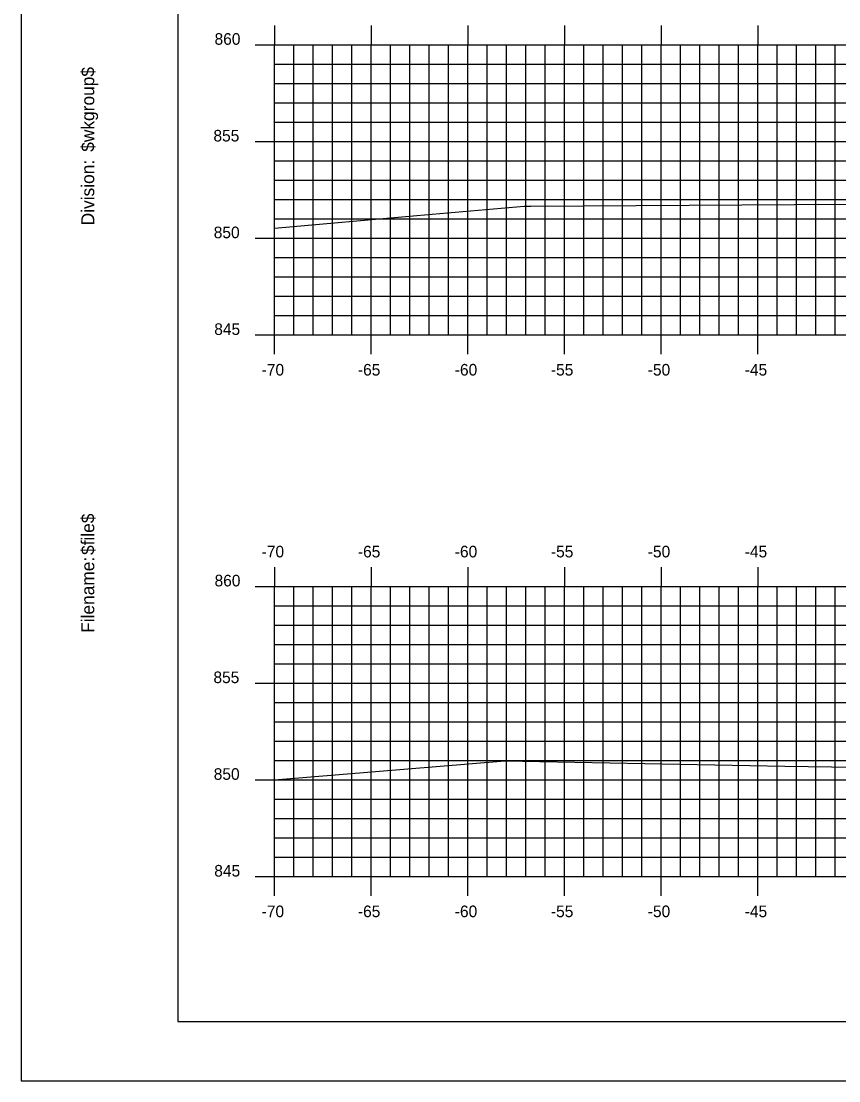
# Model space of a CAD drawing. Extents: x 2194738 to 2195190, y 863888 to 863998.
# Drawn here: x 2194837.2 to 2194879.4, y 863888.4 to 863943.2 of the extents above; entities that cross this region are included whole.
import ezdxf

# ---------------------------------------------------------------- set-up
doc = ezdxf.new("R2010")
doc.units = 0
for name, color, linetype in [('BORDER', 7, 'Continuous'), ('H_V ANNOTATION', 7, 'Continuous'), ('MAJOR', 7, 'Continuous'), ('MINOR', 7, 'Continuous'), ('PLOT BOUNDARY', 7, 'Continuous'), ('S_Roadway_Centerline', 7, 'Continuous')]:
    doc.layers.add(name, color=color, linetype=linetype)

msp = doc.modelspace()

# ---------------------------------------------------------------- linework, layer by layer
at = {"layer": 'BORDER'}
msp.add_lwpolyline([(2194845.256, 863891.446), (2195005.256, 863891.446), (2195005.256, 863996.446), (2194845.256, 863996.446)], close=True, dxfattribs=at)
at = {"layer": 'MAJOR'}
for p, q in [((2194850.256, 863942.948), (2194850.256, 863941.946)), ((2194855.256, 863942.948), (2194855.256, 863941.946)), ((2194860.256, 863942.948), (2194860.256, 863941.946)), ((2194865.256, 863942.948), (2194865.256, 863941.946)), ((2194870.256, 863942.948), (2194870.256, 863941.946)), ((2194875.256, 863942.948), (2194875.256, 863941.946)), ((2194849.254, 863941.946), (2194850.256, 863941.946)), ((2194850.256, 863941.946), (2194990.256, 863941.946)), ((2194850.256, 863926.946), (2194850.256, 863941.946)), ((2194850.256, 863926.946), (2194850.256, 863941.946)), ((2194855.256, 863926.946), (2194855.256, 863941.946)), ((2194860.256, 863926.946), (2194860.256, 863941.946)), ((2194865.256, 863926.946), (2194865.256, 863941.946)), ((2194870.256, 863926.946), (2194870.256, 863941.946)), ((2194875.256, 863926.946), (2194875.256, 863941.946)), ((2194849.254, 863936.946), (2194850.256, 863936.946)), ((2194850.256, 863936.946), (2194990.256, 863936.946)), ((2194849.254, 863931.946), (2194850.256, 863931.946)), ((2194850.256, 863931.946), (2194990.256, 863931.946)), ((2194849.254, 863926.946), (2194850.256, 863926.946)), ((2194850.256, 863926.946), (2194990.256, 863926.946)), ((2194850.256, 863925.944), (2194850.256, 863926.946)), ((2194855.256, 863925.944), (2194855.256, 863926.946)), ((2194860.256, 863925.944), (2194860.256, 863926.946)), ((2194865.256, 863925.944), (2194865.256, 863926.946)), ((2194870.256, 863925.944), (2194870.256, 863926.946)), ((2194875.256, 863925.944), (2194875.256, 863926.946)), ((2194850.256, 863914.948), (2194850.256, 863913.946)), ((2194855.256, 863914.948), (2194855.256, 863913.946)), ((2194860.256, 863914.948), (2194860.256, 863913.946)), ((2194865.256, 863914.948), (2194865.256, 863913.946)), ((2194870.256, 863914.948), (2194870.256, 863913.946)), ((2194875.256, 863914.948), (2194875.256, 863913.946)), ((2194849.254, 863913.946), (2194850.256, 863913.946)), ((2194850.256, 863913.946), (2194990.256, 863913.946)), ((2194850.256, 863898.946), (2194850.256, 863913.946)), ((2194850.256, 863898.946), (2194850.256, 863913.946)), ((2194850.256, 863913.946), (2194990.256, 863913.946)), ((2194855.256, 863898.946), (2194855.256, 863913.946)), ((2194860.256, 863898.946), (2194860.256, 863913.946)), ((2194865.256, 863898.946), (2194865.256, 863913.946)), ((2194870.256, 863898.946), (2194870.256, 863913.946)), ((2194875.256, 863898.946), (2194875.256, 863913.946)), ((2194849.254, 863908.946), (2194850.256, 863908.946)), ((2194850.256, 863908.946), (2194990.256, 863908.946)), ((2194849.254, 863903.946), (2194850.256, 863903.946)), ((2194850.256, 863903.946), (2194990.256, 863903.946)), ((2194849.254, 863898.946), (2194850.256, 863898.946)), ((2194850.256, 863898.946), (2194990.256, 863898.946)), ((2194850.256, 863897.944), (2194850.256, 863898.946)), ((2194855.256, 863897.944), (2194855.256, 863898.946)), ((2194860.256, 863897.944), (2194860.256, 863898.946)), ((2194865.256, 863897.944), (2194865.256, 863898.946)), ((2194870.256, 863897.944), (2194870.256, 863898.946)), ((2194875.256, 863897.944), (2194875.256, 863898.946))]:
    msp.add_line(p, q, dxfattribs=at)
at = {"layer": 'MINOR'}
for p, q in [((2194851.256, 863926.946), (2194851.256, 863941.946)), ((2194852.256, 863926.946), (2194852.256, 863941.946)), ((2194853.256, 863926.946), (2194853.256, 863941.946)), ((2194854.256, 863926.946), (2194854.256, 863941.946)), ((2194856.256, 863926.946), (2194856.256, 863941.946)), ((2194857.256, 863926.946), (2194857.256, 863941.946)), ((2194858.256, 863926.946), (2194858.256, 863941.946)), ((2194859.256, 863926.946), (2194859.256, 863941.946)), ((2194861.256, 863926.946), (2194861.256, 863941.946)), ((2194862.256, 863926.946), (2194862.256, 863941.946)), ((2194863.256, 863926.946), (2194863.256, 863941.946)), ((2194864.256, 863926.946), (2194864.256, 863941.946)), ((2194866.256, 863926.946), (2194866.256, 863941.946)), ((2194867.256, 863926.946), (2194867.256, 863941.946)), ((2194868.256, 863926.946), (2194868.256, 863941.946)), ((2194869.256, 863926.946), (2194869.256, 863941.946)), ((2194871.256, 863926.946), (2194871.256, 863941.946)), ((2194872.256, 863926.946), (2194872.256, 863941.946)), ((2194873.256, 863926.946), (2194873.256, 863941.946)), ((2194874.256, 863926.946), (2194874.256, 863941.946)), ((2194876.256, 863926.946), (2194876.256, 863941.946)), ((2194877.256, 863926.946), (2194877.256, 863941.946)), ((2194878.256, 863926.946), (2194878.256, 863941.946)), ((2194879.256, 863926.946), (2194879.256, 863941.946)), ((2194850.256, 863940.946), (2194990.256, 863940.946)), ((2194850.256, 863940.946), (2194851.258, 863940.946)), ((2194850.256, 863939.946), (2194990.256, 863939.946)), ((2194850.256, 863939.946), (2194851.258, 863939.946)), ((2194850.256, 863938.946), (2194990.256, 863938.946)), ((2194850.256, 863938.946), (2194851.258, 863938.946)), ((2194850.256, 863937.946), (2194990.256, 863937.946)), ((2194850.256, 863937.946), (2194851.258, 863937.946)), ((2194850.256, 863935.946), (2194990.256, 863935.946)), ((2194850.256, 863935.946), (2194851.258, 863935.946)), ((2194850.256, 863934.946), (2194990.256, 863934.946)), ((2194850.256, 863934.946), (2194851.258, 863934.946)), ((2194850.256, 863933.946), (2194990.256, 863933.946)), ((2194850.256, 863933.946), (2194851.258, 863933.946)), ((2194850.256, 863932.946), (2194990.256, 863932.946)), ((2194850.256, 863932.946), (2194851.258, 863932.946)), ((2194850.256, 863930.946), (2194990.256, 863930.946)), ((2194850.256, 863930.946), (2194851.258, 863930.946)), ((2194850.256, 863929.946), (2194990.256, 863929.946)), ((2194850.256, 863929.946), (2194851.258, 863929.946)), ((2194850.256, 863928.946), (2194990.256, 863928.946)), ((2194850.256, 863928.946), (2194851.258, 863928.946)), ((2194850.256, 863927.946), (2194990.256, 863927.946)), ((2194850.256, 863927.946), (2194851.258, 863927.946)), ((2194851.256, 863898.946), (2194851.256, 863913.946)), ((2194852.256, 863898.946), (2194852.256, 863913.946)), ((2194853.256, 863898.946), (2194853.256, 863913.946)), ((2194854.256, 863898.946), (2194854.256, 863913.946)), ((2194856.256, 863898.946), (2194856.256, 863913.946)), ((2194857.256, 863898.946), (2194857.256, 863913.946)), ((2194858.256, 863898.946), (2194858.256, 863913.946)), ((2194859.256, 863898.946), (2194859.256, 863913.946)), ((2194861.256, 863898.946), (2194861.256, 863913.946)), ((2194862.256, 863898.946), (2194862.256, 863913.946)), ((2194863.256, 863898.946), (2194863.256, 863913.946)), ((2194864.256, 863898.946), (2194864.256, 863913.946)), ((2194866.256, 863898.946), (2194866.256, 863913.946)), ((2194867.256, 863898.946), (2194867.256, 863913.946)), ((2194868.256, 863898.946), (2194868.256, 863913.946)), ((2194869.256, 863898.946), (2194869.256, 863913.946)), ((2194871.256, 863898.946), (2194871.256, 863913.946)), ((2194872.256, 863898.946), (2194872.256, 863913.946)), ((2194873.256, 863898.946), (2194873.256, 863913.946)), ((2194874.256, 863898.946), (2194874.256, 863913.946)), ((2194876.256, 863898.946), (2194876.256, 863913.946)), ((2194877.256, 863898.946), (2194877.256, 863913.946)), ((2194878.256, 863898.946), (2194878.256, 863913.946)), ((2194879.256, 863898.946), (2194879.256, 863913.946)), ((2194850.256, 863912.946), (2194990.256, 863912.946)), ((2194850.256, 863912.946), (2194851.258, 863912.946)), ((2194850.256, 863911.946), (2194990.256, 863911.946)), ((2194850.256, 863911.946), (2194851.258, 863911.946)), ((2194850.256, 863910.946), (2194990.256, 863910.946)), ((2194850.256, 863910.946), (2194851.258, 863910.946)), ((2194850.256, 863909.946), (2194990.256, 863909.946)), ((2194850.256, 863909.946), (2194851.258, 863909.946)), ((2194850.256, 863907.946), (2194990.256, 863907.946)), ((2194850.256, 863907.946), (2194851.258, 863907.946)), ((2194850.256, 863906.946), (2194990.256, 863906.946)), ((2194850.256, 863906.946), (2194851.258, 863906.946)), ((2194850.256, 863905.946), (2194990.256, 863905.946)), ((2194850.256, 863905.946), (2194851.258, 863905.946)), ((2194850.256, 863904.946), (2194990.256, 863904.946)), ((2194850.256, 863904.946), (2194851.258, 863904.946)), ((2194850.256, 863902.946), (2194990.256, 863902.946)), ((2194850.256, 863902.946), (2194851.258, 863902.946)), ((2194850.256, 863901.946), (2194990.256, 863901.946)), ((2194850.256, 863901.946), (2194851.258, 863901.946)), ((2194850.256, 863900.946), (2194990.256, 863900.946)), ((2194850.256, 863900.946), (2194851.258, 863900.946)), ((2194850.256, 863899.946), (2194990.256, 863899.946)), ((2194850.256, 863899.946), (2194851.258, 863899.946))]:
    msp.add_line(p, q, dxfattribs=at)
at = {"layer": 'PLOT BOUNDARY'}
msp.add_lwpolyline([(2194837.163, 863888.387), (2195007.163, 863888.387), (2195007.163, 863998.387), (2194837.163, 863998.387)], close=True, dxfattribs=at)
at = {"layer": 'S_Roadway_Centerline'}
for points in [[(2194850.256, 863932.472), (2194857.621, 863933.113), (2194863.174, 863933.605), (2194863.505, 863933.61), (2194890.775, 863933.767), (2194892.823, 863933.711), (2194893.448, 863933.904), (2194898.762, 863935.554), (2194900.923, 863936.26), (2194901.131, 863936.283), (2194901.34, 863936.29), (2194904.626, 863936.557), (2194906.71, 863936.685), (2194908.573, 863936.911), (2194918.35, 863937.137), (2194920.338, 863937.169), (2194922.335, 863937.142), (2194931.931, 863937.033), (2194932.342, 863937.008), (2194934.265, 863936.902), (2194936.186, 863936.495), (2194936.603, 863936.399), (2194940.327, 863935.219), (2194952.094, 863932.661)], [(2194850.256, 863903.946), (2194862.163, 863904.928), (2194876.641, 863904.659), (2194888.683, 863904.484), (2194891.949, 863905.503), (2194896.37, 863906.93), (2194900.004, 863907.039), (2194904.289, 863907.129), (2194905.874, 863907.236), (2194908.794, 863907.591), (2194913.318, 863907.695), (2194920.296, 863907.807), (2194927.306, 863907.711), (2194931.88, 863907.66), (2194933.306, 863907.572), (2194934.219, 863907.522), (2194935.131, 863907.329), (2194936.586, 863906.993), (2194949.583, 863902.874), (2194953.328, 863902.06), (2194962.598, 863900.741), (2194971.313, 863899.617), (2194975.97, 863899.247), (2194990.256, 863899.22)]]:
    msp.add_lwpolyline(points, dxfattribs=at)

# ---------------------------------------------------------------- texts
at = {"layer": 'BORDER'}
for s, p in [('$wkgroup$', (2194840.941, 863936.415)), ('Division:', (2194840.941, 863932.612)), ('$file$', (2194840.941, 863915.571)), ('Filename:', (2194840.941, 863911.544))]:
    msp.add_text(s, height=0.6696, rotation=90, dxfattribs=at).set_placement(p)
at = {"layer": 'H_V ANNOTATION'}
for s, p in [('860', (2194847.161, 863941.946)), ('855', (2194847.102, 863936.946)), ('850', (2194847.118, 863931.946)), ('845', (2194847.145, 863926.946)), ('-70', (2194849.597, 863924.846)), ('-65', (2194854.573, 863924.846)), ('-60', (2194859.582, 863924.846)), ('-55', (2194864.552, 863924.846)), ('-50', (2194869.56, 863924.846)), ('-45', (2194874.573, 863924.846)), ('-70', (2194849.597, 863915.446)), ('-65', (2194854.573, 863915.446)), ('-60', (2194859.582, 863915.446)), ('-55', (2194864.552, 863915.446)), ('-50', (2194869.56, 863915.446)), ('-45', (2194874.573, 863915.446)), ('860', (2194847.161, 863913.946)), ('855', (2194847.102, 863908.946)), ('850', (2194847.118, 863903.946)), ('845', (2194847.145, 863898.946)), ('-70', (2194849.597, 863896.846)), ('-65', (2194854.573, 863896.846)), ('-60', (2194859.582, 863896.846)), ('-55', (2194864.552, 863896.846)), ('-50', (2194869.56, 863896.846)), ('-45', (2194874.573, 863896.846))]:
    msp.add_text(s, height=0.6, dxfattribs=at).set_placement(p)

doc.saveas('drawing.dxf')
